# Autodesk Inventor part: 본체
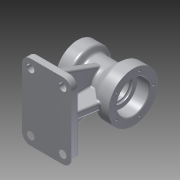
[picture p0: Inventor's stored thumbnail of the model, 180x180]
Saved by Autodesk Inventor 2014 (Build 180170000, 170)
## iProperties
Created: 2015-08
Part Number: 본체
Material: 알루미늄 6061
Document SubType Name: Modeling
Designer: Owner
Density: 2.71 g/cm^3
Appearance: 알루미늄 - 평지
Author: Owner
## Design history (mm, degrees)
sketch "스케치1"
  geometry: C1 r 40 at (0, 0); 1 further point
  constraints: 1 centre point, 1 coincident
  dimensions: "d0" = 80 diameter of C1
extrude "돌출1" new body sketch "스케치1" distance "d1" = 20; taper "d2" = 0 deg
node "작업 평면1"
sketch "스케치2"
  geometry: C1 r 35 at (0, 0); 1 further point
  constraints: 1 centre point, 1 coincident
  dimensions: "d4" = 70 diameter of C1
extrude "돌출2" join sketch "스케치2" distance "d5" = 20; taper "d6" = 0 deg
sketch "스케치3"
  geometry: L1 (0, 40)-(20, 40) reference; L2 (20, 40)-(20, -40) reference; L3 (20, -40)-(0, -40) reference; L4 (0, -40)-(0, 40) reference; L5 (-70, 35)-(-50, 35) reference; L6 (-50, 35)-(-50, -35) reference; L7 (-50, -35)-(-70, -35) reference; L8 (-70, -35)-(-70, 35) reference; L9 (0, 0)-(-50, 0); L10 (0, 40)-(-16.685, 26); L11 (0, 40)-(28.445, 40); L12 (-16.685, 26)-(-44.804, 26); L13 (-50, 35)-(-44.804, 26); L14 (-50, 35)-(-23.111, 35); L15 (-50, 35)-(-50, 0); L16 (0, 40)-(0, 0)
  constraints: 16 end point, 2 horizontal, 1 collinear, 1 midpoint, 1 perpendicular
  dimensions: "d7" = 140 deg angle of L10 L11; "d9" = 60 deg angle of L13 L14
revolve "회전1" sketch "스케치3" stored, may be unused: angle "d10" = 90 deg
node "작업 평면2"
sketch "스케치4"
  geometry: L1 (50, 35)-(50, -35) reference; L2 (70, -35)-(70, 35) reference; L3 (70, 0)-(60, 0); L4 (70, 0)-(70, -61); L5 (70, 0)-(70, 61); L6 (70, -61)-(-10, -61); L7 (70, 61)-(-10, 61); L8 (-10, 61)-(-10, -61); 1 further point
  constraints: 12 end point, 2 equal length, 2 perpendicular, 1 midpoint
  dimensions: "d12" = 10 distance of L3.start L3.end; "d19" = 80 distance of L4.end L6.end
extrude "돌출3" join sketch "스케치4" distance "d17" = 12; taper "d18" = 0 deg
sketch "스케치5"
  geometry: L1 (-44.804, -26)-(-50, -35) reference; L2 (-50, -35)-(-70, -35) reference; L3 (-70, -35)-(-70, 35) reference; L4 (-70, 35)-(-50, 35) reference; L5 (-50, 35)-(-44.804, 26) reference; L6 (-44.804, 26)-(-16.685, 26) reference; L7 (-16.685, 26)-(0, 40) reference; L8 (0, 40)-(20, 40) reference; L9 (20, 40)-(20, -40) reference; L10 (20, -40)-(0, -40) reference; L11 (0, -40)-(-16.685, -26) reference; L12 (-16.685, -26)-(-44.804, -26) reference; L13 (-70, -90)-(-70, -78) reference; L14 (-70, -78)-(10, -78) reference; L15 (10, -78)-(10, -90) reference; L16 (10, -90)-(-70, -90) reference; L17 (-70, -78)-(-60, -78); L18 (-60, -78)-(-60, -30.5); L19 (10, -78)-(0, -78); L20 (0, -78)-(9.169, -26); L21 (9.169, -26)-(-13.066, -13.163); L22 (-13.066, -13.163)-(-38.547, -15.162); L23 (-38.547, -15.162)-(-60, -30.5); 1 further point
  constraints: 14 end point, 2 perpendicular, 2 point on line
  dimensions: "d20" = 10 distance of L13.end L17.end; "d21" = 10 distance of L14.end L19.end; "d22" = 80 deg angle of L19 L20
extrude "돌출4" join sketch "스케치5" stored distance "d23" = 12; taper "d24" = 0 deg
node "작업 평면3"
sketch "스케치6"
  geometry: L1 (0, 0)-(0, 12) reference; L2 (0, 12)-(55, 12) reference; L3 (55, 12)-(55, 64.702) reference; L4 (67, 64.702)-(67, 12) reference; L5 (67, 12)-(122, 12) reference; L6 (122, 12)-(122, 0) reference; L7 (122, 0)-(0, 0) reference; L8 (0, 12)-(10, 12); L9 (10, 12)-(34.734, 79.956); L10 (10, 12)-(82.318, 12); L11 (61, 61.769)-(61, 12); L12 (61, 12)-(10, 12); L13 (61, 61.769)-(61, 90); L14 (61, 90)-(40.606, 82.563); L15 (34.734, 79.956)-(39.044, 91.799); L16 (39.044, 91.799)-(40.606, 82.563); A1 r 26 centre (61, 90) between (67, 64.702) and (55, 64.702) reference; 1 further point
  constraints: 18 end point, 2 collinear, 2 perpendicular, 1 equal length, 1 horizontal, 1 point on line
  dimensions: "d25" = 10 distance of L1.end L8.end; "d26" = 70 deg angle of L10 L9
extrude "돌출5" join sketch "스케치6" stored distance "d27" = 12; taper "d28" = 0 deg
sketch "스케치7"
  geometry: C1 r 40 at (0, 0) reference; C2 r 26 at (0, 0)
  constraints: 1 centre point, 1 coincident
  dimensions: "d29" = 52 diameter of C2
extrude "돌출6" cut sketch "스케치7" distance "d30" = 17; taper "d31" = 0 deg
sketch "스케치8"
  geometry: C1 r 35 at (0, 0) reference; C2 r 20 at (0, 0)
  constraints: 1 centre point, 1 coincident
  dimensions: "d32" = 40 diameter of C2
extrude "돌출7" cut sketch "스케치8" distance "d33" = 20; taper "d34" = 0 deg
sketch "스케치9"
  geometry: C1 r 20 at (0, 0) reference; C2 r 16 at (0, 0)
  constraints: 1 centre point, 1 coincident
  dimensions: "d82" = 32 diameter of C2
node "작업 평면4"
sketch "스케치12" dims "d55" = 54
  geometry: C1 r 35 at (0, 0) reference; C2 r 2 at (0, 27); 1 further point
  constraints: 1 centre point, 1 coincident, 1 vertical alignment, 2 other
  dimensions: "d56" = 4 diameter of C2
hole "구멍2" sketch "스케치12" at (0, 27) diameter "d57" = 3.242; stored, may be unused: countersink angle "d61" = 90 deg, drill point angle "d63" = 118 deg; dims "d58" = 10, "d59" = 4, "d60" = 2, "d62" = 13
sketch "스케치14" dims "d67" = 66
  geometry: C1 r 40 at (0, 0) reference; C2 r 2 at (0, 33); 1 further point
  constraints: 1 centre point, 1 coincident, 1 vertical alignment, 2 other
  dimensions: "d68" = 4 diameter of C2
hole "구멍3" sketch "스케치14" at (0, 33) diameter "d69" = 3.242; stored, may be unused: countersink angle "d73" = 90 deg, drill point angle "d75" = 118 deg; dims "d70" = 10, "d71" = 4, "d72" = 2, "d74" = 13
sketch "스케치15"
  geometry: C1 r 26 at (0, 0) reference; C2 r 26 at (0, 0)
  constraints: 1 centre point, 1 coincident, 1 concentric
extrude "돌출11" cut sketch "스케치9" distance "d83" = 70; taper "d84" = 0 deg
sketch "스케치16"
  geometry: L1 (86.091, 83.185)-(112, 12) reference; L2 (67, 12)-(112, 12) reference; L3 (67, 64.702)-(67, 12) reference; L4 (55, 12)-(55, 64.702) reference; L5 (10, 12)-(55, 12) reference; L6 (10, 12)-(35.909, 83.185) reference; L7 (112, 12)-(122, 12) reference; L8 (122, 12)-(122, 0) reference; L9 (122, 0)-(0, 0) reference; L10 (0, 0)-(0, 12) reference; L11 (0, 12)-(10, 12) reference; L12 (55, 12)-(61, 12); L13 (61, 12)-(61, 30); L14 (37, 42)-(37, 36); L15 (31, 36)-(31, 30); L16 (43, 36)-(43, 30); L17 (85, 30)-(85, 24); L18 (79, 36)-(79, 30); L19 (91, 36)-(91, 30); C1 r 16 at (61, 90) reference; A1 r 26 centre (61, 90) between (35.909, 83.185) and (55, 64.702) reference; A2 r 26 centre (61, 90) between (86.091, 83.185) and (35.909, 83.185) reference; A3 r 26 centre (61, 90) between (67, 64.702) and (86.091, 83.185) reference; A4 r 6 centre (37, 30) between (31, 30) and (43, 30); A5 r 6 centre (37, 36) between (43, 36) and (31, 36); A6 r 6 centre (85, 30) between (79, 30) and (91, 30); A7 r 6 centre (85, 36) between (91, 36) and (79, 36)
  constraints: 16 end point, 11 point on circle, 5 tangent, 4 centre point, 4 parallel, 1 collinear, 1 perpendicular
  dimensions: "d85" = 18 distance of L12.end L13.end; "d87" = 24 distance of L13.end L17.start
extrude "돌출12" cut sketch "스케치16" distance "d91" = 70; taper "d92" = 0 deg
fillet "모깎기1" dims "d93" = 14
sketch "스케치17"
  geometry: A1 r 14 centre (-56, -47) between (-70, -47) and (-56, -61) reference; A2 r 14 centre (-4, -47) between (-4, -61) and (10, -47) reference; A3 r 14 centre (-4, 47) between (10, 47) and (-4, 61) reference; A4 r 14 centre (-56, 47) between (-56, 61) and (-70, 47) reference; 1 further point
hole "구멍4" sketch "스케치17" at (-56, -47), (-4, -47), (-4, 47), (-56, 47) diameter "d94" = 12; stored, may be unused: countersink angle "d98" = 90 deg, drill point angle "d100" = 0 deg; dims "d95" = 10, "d96" = 4, "d97" = 2, "d99" = 30
sketch "스케치18"
  geometry: L1 (-36, -78)-(-60, -78) reference; L2 (-60, -78)-(-44, -78); L3 (-44, -78)-(-44, -54); 2 further points
  constraints: 4 end point, 1 coincident, 1 perpendicular, 1 point on line, 1 other
  dimensions: "d101" = 16 distance of L1.end L2.end; "d102" = 24 distance of L2.end L3.end
feature "엠보싱1" sketch "스케치18" dims "d103" = 0.5, "d104" = 0
fillet "모깎기2" dims "d105" = 5
chamfer "모따기1" distance "d106" = 1; stored, may be unused: second distance "d107" = 2, angle "d108" = 45 deg
fillet "모깎기5" dims "d111" = 3
fillet "모깎기6" dims "d112" = 3
fillet "모깎기7" dims "d113" = 3
fillet "모깎기8" dims "d114" = 3
fillet "모깎기9" dims "d115" = 3
fillet "모깎기10" dims "d116" = 3
fillet "모깎기11" dims "d117" = 3
extrude "돌출13" cut sketch "스케치15" distance "d118" = 3; taper "d119" = 0 deg
sketch "스케치19"
  geometry: C1 r 16 at (0, 0) reference; C2 r 26 at (0, 0) reference; C3 r 19 at (0, 0)
  constraints: 1 centre point, 1 coincident
  dimensions: "d120" = 38 diameter of C3
extrude "돌출14" cut sketch "스케치19" distance "d121" = 3; taper "d122" = 0 deg
fillet "모깎기12" dims "d123" = 3
sketch "스케치20"
  geometry: C1 r 16 at (0, 0) reference; C2 r 20 at (0, 0) reference; C3 r 20 at (0, 0)
  constraints: 1 centre point, 1 coincident, 1 concentric
extrude "돌출15" cut sketch "스케치20" distance "d125" = 3; taper "d126" = 0 deg
fillet "모깎기14" dims "d127" = 0.3
node "솔리드1"
mirror "대칭1"
pattern_circular "원형 패턴2" dims angle "d65" = 360 deg
pattern_circular "원형 패턴3" dims angle "d77" = 360 deg
node "투영된 루프1"
node "절단 모서리 투영1"
node "절단 모서리 투영2"
node "절단 모서리 투영3"
node "절단 모서리 투영4"
